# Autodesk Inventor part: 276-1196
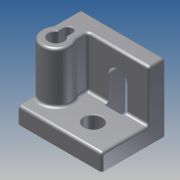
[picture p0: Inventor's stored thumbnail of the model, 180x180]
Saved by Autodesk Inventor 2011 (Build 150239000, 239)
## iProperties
Company: Autodesk Inc.
Created: 2010-04
Part Number: 276-1196
Document SubType Name: Modeling
Designer: Autodesk Inc.
Density: 1 g/cm^3
Catalog Web Link: http://www.vexrobotics.com/276-1196.html
Description: The Antenna Tube and holder help protect the Receiver's antenna and keep it away from metal. The cable connects the Receiver to
Vendor: Innovation First, Inc.
Author: Autodesk Inc.
Title: VEX Robotics Kit of Parts
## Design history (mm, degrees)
sketch "Sketch1"
  geometry: L1 (0, 0)-(4.064, 0); L2 (4.064, 0)-(4.064, 15.621); L3 (4.064, 15.621)-(-12.395, 15.621); L4 (-12.395, 15.621)-(-12.395, 11.557); L5 (-12.395, 11.557)-(0, 11.557); L6 (0, 11.557)-(0, 0)
  constraints: 12 end point, 4 parallel, 1 horizontal, 1 perpendicular
  dimensions: "d0" = 4.064 distance of L1.start L1.end; "d1" = 15.621 distance of L1.end L2.end; "d2" = 16.4592 distance of L2.end L3.end; "d3" = 4.064 distance of L3.end L4.end
extrude "Extrusion1" new body sketch "Sketch1" distance "d4" = 20.701; taper "d5" = 0 deg
sketch "Sketch2"
  geometry: L1 (0, 4.064)-(-20.701, 4.064) reference; L2 (-14.986, -2.709)-(-14.986, 0); L3 (-0.635, 4.064)-(-20.066, 4.064); L4 (0, 4.064)-(-20.701, 4.064); L5 (-18.859, -3.367)-(-18.859, -1.905); L6 (-16.827, -1.905)-(-16.827, -3.367); L7 (-20.701, 0)-(-14.986, 0); L8 (-20.701, 0)-(-20.701, -2.709); A1 r 3.556 centre (-17.843, -4.826) between (-20.701, -2.709) and (-14.986, -2.709); A2 r 1.016 centre (-17.843, -1.905) between (-16.827, -1.905) and (-18.859, -1.905); A3 r 1.778 centre (-17.843, -4.826) between (-18.859, -3.367) and (-16.827, -3.367); 2 further points
  constraints: 14 end point, 6 point on circle, 3 centre point, 2 perpendicular
sketch "Sketch3"
  geometry: L1 (16.459, 5.334)-(6.35, 5.334); L2 (6.35, 9.906)-(16.459, 9.906); L3 (1.651, 3.556)-(16.459, 3.556); L4 (1.651, 1.651)-(1.651, 3.556); L5 (16.459, 1.651)-(1.651, 1.651); L6 (16.459, 11.684)-(1.651, 11.684); L7 (1.651, 19.05)-(16.459, 19.05); L8 (1.651, 11.684)-(1.651, 19.05); L9 (16.459, 0)-(16.459, 20.701) reference; A1 r 2.286 centre (6.35, 7.62) between (6.35, 9.906) and (6.35, 5.334); 1 further point
  constraints: 16 end point, 6 point on line, 2 point on circle, 1 centre point
sketch "Sketch4"
  geometry: L1 (3.556, 9.08)-(6.826, 9.081); L2 (9.906, 10.605)-(5.334, 10.604); L3 (11.684, 9.08)-(11.684, 15.621); L4 (9.906, 15.621)-(9.906, 10.605); L5 (3.556, 15.621)-(3.556, 9.08); L6 (5.334, 10.604)-(5.334, 15.621); L7 (8.604, 8.899)-(8.604, 9.08); L8 (6.826, 9.081)-(6.826, 8.899); L9 (1.651, 1.778)-(1.651, 15.621); L10 (8.604, 9.08)-(11.684, 9.08); L11 (6.826, 1.778)-(1.651, 1.778); L12 (6.826, 2.341)-(6.826, 1.778); L13 (8.604, 1.778)-(8.604, 2.341); L14 (19.05, 15.621)-(19.05, 1.778); L15 (19.05, 1.778)-(8.604, 1.778); L16 (1.651, 15.621)-(3.556, 15.621); L17 (11.684, 15.621)-(19.05, 15.621); C1 r 2.127 at (7.715, 5.62); A1 r 3.397 centre (7.715, 5.62) between (6.826, 8.899) and (6.826, 2.341); A2 r 3.397 centre (7.715, 5.62) between (8.604, 2.341) and (8.604, 8.899)
  constraints: 34 end point, 4 point on circle, 3 centre point, 1 collinear
extrude "Extrusion3" cut sketch "Sketch4" distance "d11" = 2.54; taper "d12" = 0 deg
extrude "Extrusion4" cut sketch "Sketch4" distance "d13" = 5.0292; taper "d14" = 0 deg
extrude "Extrusion5" join sketch "Sketch2" stored distance "d23" = 6.0833; taper "d24" = 0 deg
sketch "Sketch5"
  geometry: A1 r 3.397 centre (7.715, 5.62) between (8.604, 2.341) and (8.604, 8.899) reference
hole "Hole1" sketch "Sketch5" at (7.715, 5.62) diameter "d15" = 4.2672; stored, may be unused: countersink angle "d19" = 82 deg, drill point angle "d21" = 118 deg; dims "d16" = 19.05, "d17" = 9.525, "d18" = 6.35, "d20" = 25.4
body "Solid1"
extrude "Extrusion2" cut sketch "Sketch3" distance "d9" = 1.905; taper "d10" = 0 deg
fillet "Fillet1" dims "d25" = 0.635, "d26" = 0.254
